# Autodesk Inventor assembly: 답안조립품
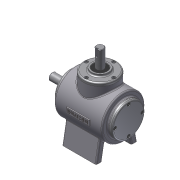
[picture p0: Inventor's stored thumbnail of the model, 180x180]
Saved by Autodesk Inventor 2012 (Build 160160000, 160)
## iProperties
Created: 2015-01
Part Number: 답안조립품
Document SubType Name: Assembly
Designer: Class3-User
Author: Class3-User
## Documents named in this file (15)
- C:\Users\Class3-User\Desktop\450106V1005\답안조립품.iam
- C:\Users\Class3-User\Desktop\450106V1005\본체.ipt
- C:\Users\Class3-User\Desktop\450106V1005\메인 축.ipt
- 메인 축.ipt
- C:\Users\Class3-User\Desktop\450106V1005\커버.ipt
- C:\Users\Class3-User\Desktop\450106V1005\베어링 6203.ipt
- C:\Users\Class3-User\Desktop\450106V1005\오일실.ipt
- C:\Users\Class3-User\Desktop\450106V1005\키 5x5.ipt
- C:\Users\Class3-User\Desktop\450106V1005\서브 축.ipt
- 서브 축.ipt
- C:\Users\Class3-User\Desktop\450106V1005\메인 베벨기어.ipt
- C:\Users\Class3-User\Desktop\450106V1005\커버2.ipt
- C:\Users\Class3-User\Desktop\450106V1005\키 4x4.ipt
- C:\Users\Class3-User\Desktop\450106V1005\서브 베벨기어.ipt
- C:\Users\Class3-User\Desktop\450106V1005\M4.ipt
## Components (8 placed, 1 different names)
1. M4:1
2. M4:2
3. M4:3
4. M4:4
5. M4:5
6. M4:6
7. M4:7
8. M4:8
